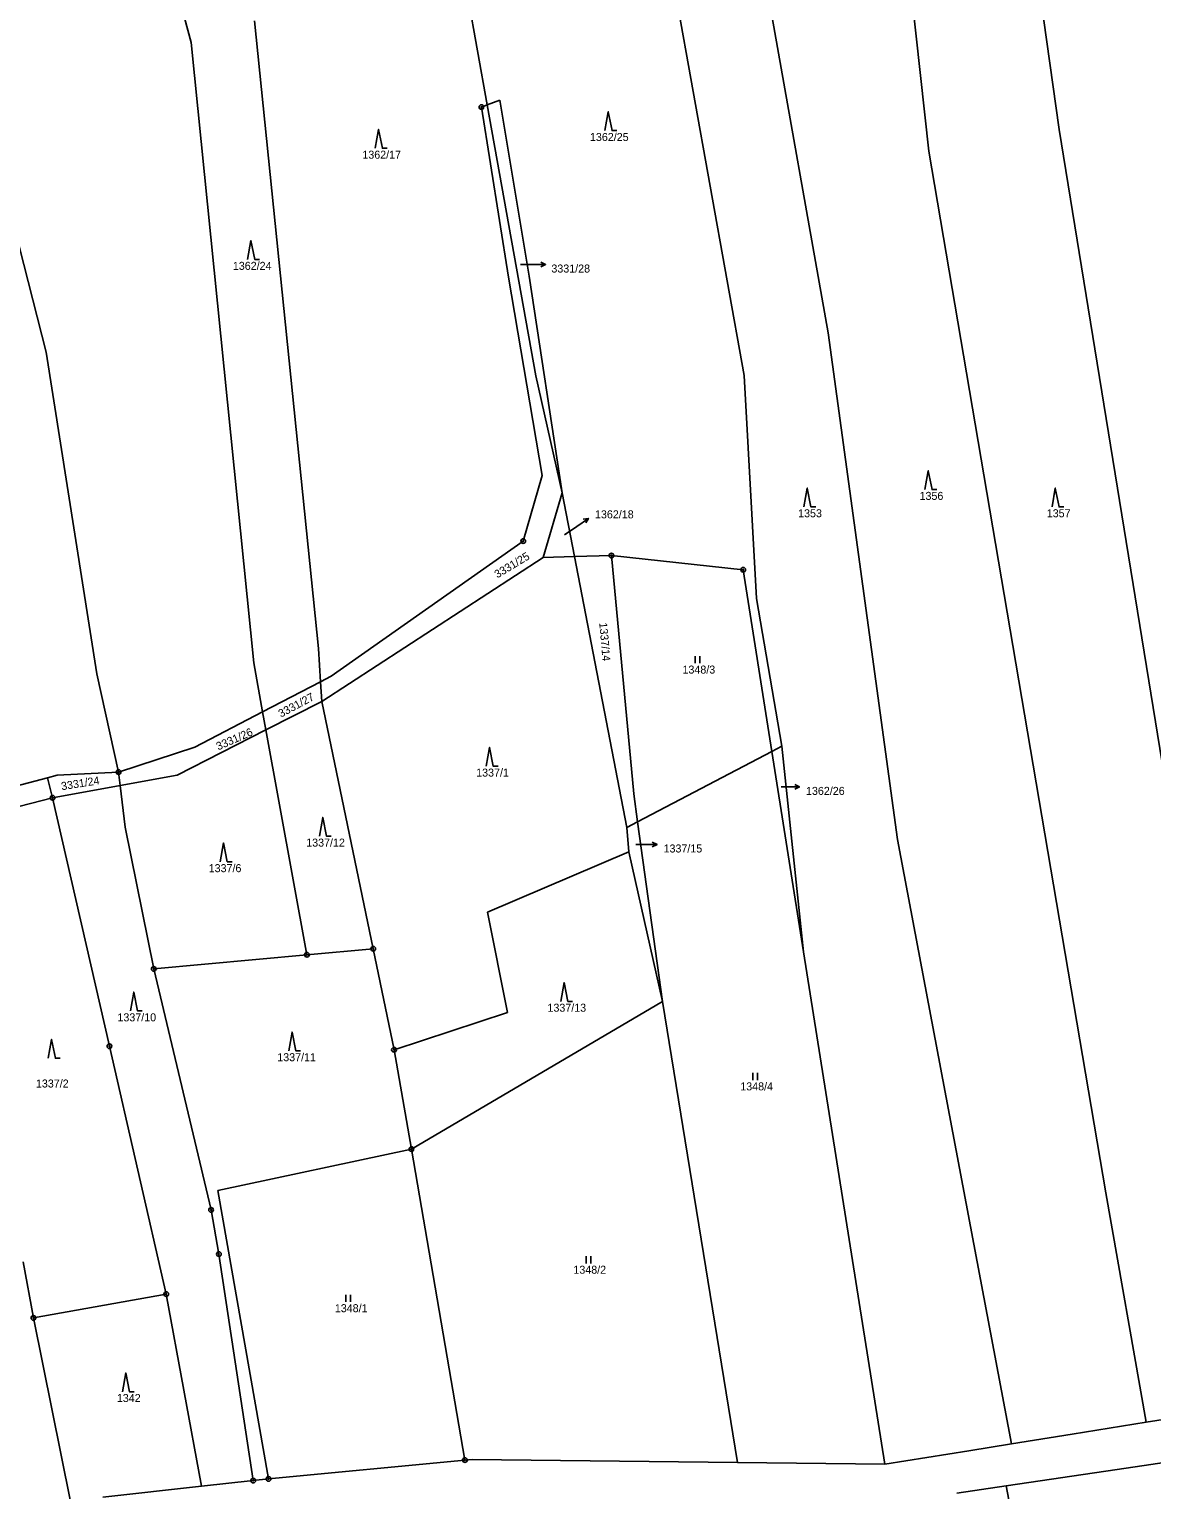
# Model space of a CAD drawing. Extents: x -763205 to -760228, y -1155311 to -1152844.
# Drawn here: x -760753.2 to -760514.7, y -1154798.5 to -1154488.2 of the extents above; entities that cross this region are included whole.
import ezdxf

# ---------------------------------------------------------------- set-up
doc = ezdxf.new("R2010")
doc.units = 0
for name, color, linetype in [('Vrstva 1', 7, 'Continuous'), ('Vrstva 16', 7, 'Continuous'), ('Vrstva 18', 7, 'Continuous'), ('Vrstva 24', 7, 'Continuous'), ('Vrstva 25', 7, 'Continuous'), ('Vrstva 6', 7, 'Continuous')]:
    doc.layers.add(name, color=color, linetype=linetype)

msp = doc.modelspace()

# ---------------------------------------------------------------- linework, layer by layer
at = {"layer": 'Vrstva 1'}
for p, q in [((-760657.16, -1154504.77), (-760655.93, -1154504.3)), ((-760657.16, -1154504.77), (-760651.42, -1154540.91)), ((-760655.93, -1154504.3), (-760653.23, -1154503.28)), ((-760653.23, -1154503.28), (-760647.01, -1154540.72)), ((-760651.42, -1154540.91), (-760644.28, -1154583.06)), ((-760647.01, -1154540.72), (-760640.02, -1154586.71)), ((-760648.28, -1154596.96), (-760644.28, -1154583.06)), ((-760644.03, -1154600.42), (-760640.02, -1154586.71)), ((-760689.09, -1154625.66), (-760648.28, -1154596.96)), ((-760691.06, -1154631), (-760644.03, -1154600.42)), ((-760644.03, -1154600.42), (-760637.4, -1154600.25)), ((-760637.4, -1154600.25), (-760629.55, -1154600.05)), ((-760629.55, -1154600.05), (-760601.54, -1154603.04)), ((-760629.55, -1154600.05), (-760624.81, -1154650.64)), ((-760601.54, -1154603.04), (-760595.43, -1154641.62)), ((-760691.34, -1154626.83), (-760689.09, -1154625.66)), ((-760703.65, -1154633.24), (-760691.34, -1154626.83)), ((-760702.95, -1154637.07), (-760691.06, -1154631)), ((-760718.02, -1154640.73), (-760703.65, -1154633.24)), ((-760721.78, -1154646.68), (-760702.95, -1154637.07)), ((-760734.25, -1154646.01), (-760718.02, -1154640.73)), ((-760595.43, -1154641.62), (-760588.7, -1154684.17)), ((-760767.66, -1154652.01), (-760749.33, -1154647.21)), ((-760749.33, -1154647.21), (-760747.27, -1154646.67)), ((-760747.27, -1154646.67), (-760734.25, -1154646.01)), ((-760733.92, -1154648.88), (-760721.78, -1154646.68)), ((-760748.29, -1154651.48), (-760733.92, -1154648.88)), ((-760624.81, -1154650.64), (-760623.98, -1154656.62)), ((-760766.18, -1154656.14), (-760748.29, -1154651.48)), ((-760748.29, -1154651.48), (-760736.19, -1154704.25)), ((-760623.98, -1154656.62), (-760618.68, -1154694.73)), ((-760726.79, -1154687.83), (-760694.23, -1154684.82)), ((-760694.23, -1154684.82), (-760680.14, -1154683.56)), ((-760680.14, -1154683.56), (-760675.73, -1154705.01)), ((-760588.7, -1154684.17), (-760571.46, -1154793.04)), ((-760726.79, -1154687.83), (-760714.6, -1154739.02)), ((-760672.02, -1154726.09), (-760618.68, -1154694.73)), ((-760736.19, -1154704.25), (-760724.12, -1154756.91)), ((-760675.73, -1154705.01), (-760672.02, -1154726.09)), ((-760713.16, -1154734.91), (-760672.02, -1154726.09)), ((-760672.02, -1154726.09), (-760660.65, -1154792.14)), ((-760713.16, -1154734.91), (-760702.39, -1154796.14)), ((-760714.6, -1154739.02), (-760712.93, -1154748.41)), ((-760754.52, -1154750.05), (-760752.34, -1154761.96)), ((-760712.93, -1154748.41), (-760705.63, -1154796.5)), ((-760752.34, -1154761.96), (-760724.12, -1154756.91)), ((-760515.9, -1154784.12), (-760491.19, -1154780.15)), ((-760531.61, -1154786.64), (-760515.9, -1154784.12)), ((-760544.55, -1154788.72), (-760531.61, -1154786.64)), ((-760571.46, -1154793.04), (-760553.57, -1154790.17)), ((-760553.57, -1154790.17), (-760544.55, -1154788.72)), ((-760522.11, -1154794.14), (-760495.56, -1154790.19)), ((-760702.39, -1154796.14), (-760660.65, -1154792.14)), ((-760660.65, -1154792.14), (-760659.14, -1154792)), ((-760659.14, -1154792), (-760602.74, -1154792.67)), ((-760602.74, -1154792.67), (-760571.46, -1154793.04)), ((-760716.64, -1154797.71), (-760705.63, -1154796.5)), ((-760705.63, -1154796.5), (-760702.39, -1154796.14)), ((-760545.65, -1154797.64), (-760522.11, -1154794.14)), ((-760737.63, -1154800.03), (-760716.64, -1154797.71)), ((-760556.17, -1154799.21), (-760545.65, -1154797.64))]:
    msp.add_line(p, q, dxfattribs=at)
at = {"layer": 'Vrstva 16'}
for p, q in [((-760648.83, -1154538.22), (-760646.53, -1154538.22)), ((-760643.53, -1154538.221), (-760646.53, -1154538.22)), ((-760634.424, -1154592.132), (-760636.89, -1154593.84)), ((-760639.52, -1154595.66), (-760636.89, -1154593.84)), ((-760593.47, -1154649.17), (-760592.59, -1154649.17)), ((-760589.59, -1154649.171), (-760592.59, -1154649.17)), ((-760624.34, -1154661.4), (-760622.85, -1154661.4)), ((-760619.85, -1154661.401), (-760622.85, -1154661.4))]:
    msp.add_line(p, q, dxfattribs=at)
for points in [[(-760644.53, -1154537.721), (-760643.53, -1154538.221), (-760644.53, -1154538.721)], [(-760635.53, -1154592.29), (-760634.424, -1154592.132), (-760634.961, -1154593.113)], [(-760590.59, -1154648.671), (-760589.59, -1154649.171), (-760590.59, -1154649.671)], [(-760620.85, -1154660.901), (-760619.85, -1154661.401), (-760620.85, -1154661.901)]]:
    msp.add_lwpolyline(points, dxfattribs=at)
at = {"layer": 'Vrstva 24'}
for centre, radius in [((-760657.16, -1154504.77), 0.5), ((-760657.16, -1154504.77), 0.1), ((-760648.28, -1154596.96), 0.5), ((-760648.28, -1154596.96), 0.1), ((-760629.55, -1154600.05), 0.5), ((-760629.55, -1154600.05), 0.1), ((-760601.54, -1154603.04), 0.5), ((-760601.54, -1154603.04), 0.1), ((-760734.25, -1154646.01), 0.5), ((-760734.25, -1154646.01), 0.1), ((-760748.29, -1154651.48), 0.5), ((-760748.29, -1154651.48), 0.1), ((-760694.23, -1154684.82), 0.5), ((-760694.23, -1154684.82), 0.1), ((-760680.14, -1154683.56), 0.5), ((-760680.14, -1154683.56), 0.1), ((-760726.79, -1154687.83), 0.5), ((-760726.79, -1154687.83), 0.1), ((-760736.19, -1154704.25), 0.5), ((-760736.19, -1154704.25), 0.1), ((-760675.73, -1154705.01), 0.5), ((-760675.73, -1154705.01), 0.1), ((-760672.02, -1154726.09), 0.5), ((-760672.02, -1154726.09), 0.1), ((-760714.6, -1154739.02), 0.5), ((-760714.6, -1154739.02), 0.1), ((-760712.93, -1154748.41), 0.5), ((-760712.93, -1154748.41), 0.1), ((-760724.12, -1154756.91), 0.5), ((-760724.12, -1154756.91), 0.1), ((-760752.34, -1154761.96), 0.5), ((-760752.34, -1154761.96), 0.1), ((-760660.65, -1154792.14), 0.5), ((-760660.65, -1154792.14), 0.1), ((-760705.63, -1154796.5), 0.5), ((-760705.63, -1154796.5), 0.1), ((-760702.39, -1154796.14), 0.5), ((-760702.39, -1154796.14), 0.1)]:
    msp.add_circle(centre, radius, dxfattribs=at)
at = {"layer": 'Vrstva 25'}
for p, q in [((-760611.72, -1154622.9), (-760611.72, -1154621.4)), ((-760610.72, -1154622.9), (-760610.72, -1154621.4)), ((-760599.52, -1154711.43), (-760599.52, -1154709.93)), ((-760598.52, -1154711.43), (-760598.52, -1154709.93)), ((-760634.92, -1154750.37), (-760634.92, -1154748.87)), ((-760633.92, -1154750.37), (-760633.92, -1154748.87)), ((-760685.98, -1154758.54), (-760685.98, -1154757.04)), ((-760684.98, -1154758.54), (-760684.98, -1154757.04))]:
    msp.add_line(p, q, dxfattribs=at)
for points in [[(-760630.91, -1154509.78), (-760630.21, -1154505.78), (-760629.41, -1154509.78), (-760628.41, -1154509.78)], [(-760679.71, -1154513.54), (-760679.01, -1154509.54), (-760678.21, -1154513.54), (-760677.21, -1154513.54)], [(-760706.83, -1154537.15), (-760706.13, -1154533.15), (-760705.33, -1154537.15), (-760704.33, -1154537.15)], [(-760562.92, -1154586.01), (-760562.22, -1154582.01), (-760561.42, -1154586.01), (-760560.42, -1154586.01)], [(-760588.64, -1154589.7), (-760587.94, -1154585.7), (-760587.14, -1154589.7), (-760586.14, -1154589.7)], [(-760535.92, -1154589.7), (-760535.22, -1154585.7), (-760534.42, -1154589.7), (-760533.42, -1154589.7)], [(-760656.13, -1154644.78), (-760655.43, -1154640.78), (-760654.63, -1154644.78), (-760653.63, -1154644.78)], [(-760691.57, -1154659.65), (-760690.87, -1154655.65), (-760690.07, -1154659.65), (-760689.07, -1154659.65)], [(-760712.65, -1154665.08), (-760711.95, -1154661.08), (-760711.15, -1154665.08), (-760710.15, -1154665.08)], [(-760640.29, -1154694.72), (-760639.59, -1154690.72), (-760638.79, -1154694.72), (-760637.79, -1154694.72)], [(-760731.72, -1154696.76), (-760731.02, -1154692.76), (-760730.22, -1154696.76), (-760729.22, -1154696.76)], [(-760749.18, -1154706.8), (-760748.48, -1154702.8), (-760747.68, -1154706.8), (-760746.68, -1154706.8)], [(-760698.09, -1154705.23), (-760697.39, -1154701.23), (-760696.59, -1154705.23), (-760695.59, -1154705.23)], [(-760733.44, -1154777.62), (-760732.74, -1154773.62), (-760731.94, -1154777.62), (-760730.94, -1154777.62)]]:
    msp.add_lwpolyline(points, dxfattribs=at)
at = {"layer": 'Vrstva 6'}
for p, q in [((-760549.69, -1154400.46), (-760534.39, -1154509.56)), ((-760574.12, -1154405.02), (-760562.13, -1154514.13)), ((-760737.54, -1154421.53), (-760718.8, -1154491.08)), ((-760669.51, -1154428.39), (-760655.93, -1154504.3)), ((-760617.44, -1154472.29), (-760601.32, -1154561.82)), ((-760597.51, -1154473.75), (-760583.48, -1154552.72)), ((-760705.34, -1154486.45), (-760691.8, -1154619.78)), ((-760766.72, -1154490.03), (-760749.66, -1154556.8)), ((-760718.8, -1154491.08), (-760705.55, -1154622.83)), ((-760655.93, -1154504.3), (-760645.63, -1154561.89)), ((-760534.39, -1154509.56), (-760502.02, -1154708.86)), ((-760562.13, -1154514.13), (-760524.47, -1154735.42)), ((-760583.48, -1154552.72), (-760568.73, -1154660.32)), ((-760749.66, -1154556.8), (-760738.91, -1154625.17)), ((-760645.63, -1154561.89), (-760640.02, -1154586.71)), ((-760601.32, -1154561.82), (-760598.72, -1154609.15)), ((-760640.02, -1154586.71), (-760637.4, -1154600.25)), ((-760637.4, -1154600.25), (-760626.27, -1154657.82)), ((-760598.72, -1154609.15), (-760593.35, -1154640.53)), ((-760691.8, -1154619.78), (-760691.34, -1154626.83)), ((-760705.55, -1154622.83), (-760703.65, -1154633.24)), ((-760738.91, -1154625.17), (-760734.25, -1154646.01)), ((-760691.34, -1154626.83), (-760691.06, -1154631)), ((-760691.06, -1154631), (-760680.14, -1154683.56)), ((-760703.65, -1154633.24), (-760702.95, -1154637.07)), ((-760702.95, -1154637.07), (-760694.23, -1154684.82)), ((-760623.98, -1154656.62), (-760595.43, -1154641.62)), ((-760595.43, -1154641.62), (-760593.35, -1154640.53)), ((-760593.35, -1154640.53), (-760588.7, -1154684.17)), ((-760749.33, -1154647.21), (-760748.29, -1154651.48)), ((-760734.25, -1154646.01), (-760733.92, -1154648.88)), ((-760733.92, -1154648.88), (-760732.88, -1154657.75)), ((-760626.27, -1154657.82), (-760623.98, -1154656.62)), ((-760732.88, -1154657.75), (-760726.79, -1154687.83)), ((-760626.27, -1154657.82), (-760625.83, -1154662.99)), ((-760568.73, -1154660.32), (-760544.55, -1154788.72)), ((-760655.86, -1154675.76), (-760625.83, -1154662.99)), ((-760625.83, -1154662.99), (-760618.68, -1154694.73)), ((-760655.86, -1154675.76), (-760651.65, -1154697.06)), ((-760675.73, -1154705.01), (-760651.65, -1154697.06)), ((-760618.68, -1154694.73), (-760602.74, -1154792.67)), ((-760524.47, -1154735.42), (-760515.9, -1154784.12)), ((-760724.12, -1154756.91), (-760716.64, -1154797.71)), ((-760752.34, -1154761.96), (-760744.44, -1154800.93)), ((-760545.65, -1154797.64), (-760538.64, -1154834.86))]:
    msp.add_line(p, q, dxfattribs=at)

# ---------------------------------------------------------------- texts
at = {"layer": 'Vrstva 16'}
for s, p in [('3331/28', (-760642.293, -1154539.92)), ('1362/18', (-760633.027, -1154592.13)), ('1362/26', (-760588.197, -1154650.87)), ('1337/15', (-760618.457, -1154663.1))]:
    msp.add_text(s, height=1.7, dxfattribs=at).set_placement(p)
at = {"layer": 'Vrstva 18'}
for s, height, p in [('1362/25', 1.7, (-760634.097, -1154511.98)), ('1362/17', 1.7, (-760682.457, -1154515.74)), ('1362/24', 1.7, (-760709.977, -1154539.35)), ('3331/28', 0.1, (-760648.816, -1154538.22)), ('1356', 1.7, (-760564.067, -1154588.21)), ('1353', 1.7, (-760589.867, -1154591.9)), ('1357', 1.7, (-760537.037, -1154591.9)), ('1362/18', 0.1, (-760639.497, -1154595.66)), ('1348/3', 1.7, (-760614.437, -1154625.1)), ('1337/1', 1.7, (-760658.277, -1154646.98)), ('1362/26', 0.1, (-760593.447, -1154649.17)), ('1337/12', 1.7, (-760694.387, -1154661.85)), ('1337/15', 0.1, (-760624.317, -1154661.4)), ('1337/6', 1.7, (-760715.107, -1154667.28)), ('1337/10', 1.7, (-760734.497, -1154698.96)), ('1337/13', 1.7, (-760643.127, -1154696.92)), ('1337/11', 1.7, (-760700.537, -1154707.43)), ('1337/2', 1.7, (-760751.817, -1154713.02)), ('1348/4', 1.7, (-760602.157, -1154713.63)), ('1348/2', 1.7, (-760637.617, -1154752.57)), ('1348/1', 1.7, (-760688.307, -1154760.74)), ('1342', 1.7, (-760734.617, -1154779.82))]:
    msp.add_text(s, height=height, dxfattribs=at).set_placement(p)
for s, rotation, p in [('3331/25', 31.1689, (-760653.767, -1154604.907)), ('1337/14', 275.07704, (-760632.135, -1154614.331)), ('3331/27', 28.18952, (-760699.751, -1154634.478)), ('3331/26', 23.77775, (-760713.073, -1154641.434)), ('3331/24', 9.16732, (-760746.316, -1154649.892))]:
    msp.add_text(s, height=1.7, rotation=rotation, dxfattribs=at).set_placement(p)

doc.saveas('drawing.dxf')
